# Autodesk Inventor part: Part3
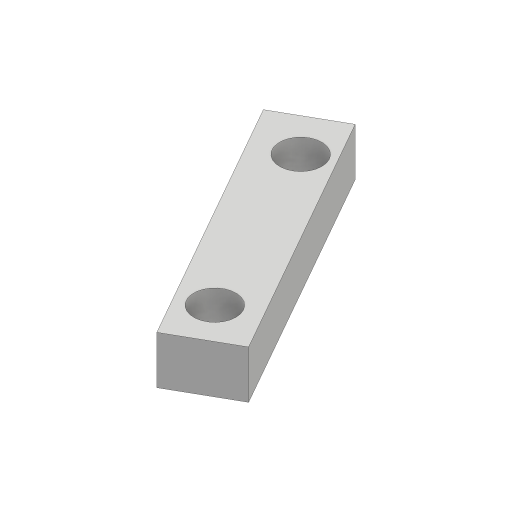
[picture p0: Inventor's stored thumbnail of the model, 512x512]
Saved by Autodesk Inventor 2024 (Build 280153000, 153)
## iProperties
Created: 2017-05
Part Number: Part3
Material: Generic
Document SubType Name: Modeling
Designer: CADCIM 00
Density: 1 g/cm^3
Appearance: Default
Author: CADCIM 00
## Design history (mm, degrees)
sketch "Sketch1"
  geometry: L1 (-30.267, 40.394)-(-1.138, -10.969); L2 (-1.138, -10.969)-(11.085, -4.037); L3 (11.085, -4.037)-(-18.043, 47.326); L4 (-18.043, 47.326)-(-30.267, 40.394); C1 r 4.406 at (-18.304, 36.224) reference; C2 r 4.406 at (0, 0) reference; 1 further point
  constraints: 8 end point, 2 parallel, 1 perpendicular
extrude "Extrusion1" new body sketch "Sketch1" distance "d0" = 10; taper "d1" = 0 deg
body "Solid1"
node "Reference1"
node "Reference2"
